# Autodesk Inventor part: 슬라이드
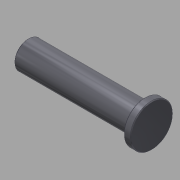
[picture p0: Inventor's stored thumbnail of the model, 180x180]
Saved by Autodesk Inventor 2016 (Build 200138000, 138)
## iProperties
Created: 2015-10
Part Number: 슬라이드
Document SubType Name: Modeling
Designer: mdu
Density: 7.86 g/cm^3
Material: 강철, 연강
Appearance: 강철 - 광택
Mass: 1603.27 g
Surface Area: 269.019 cm^2
Volume: 203.978 cm^3
Author: mdu
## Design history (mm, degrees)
sketch "스케치1"
  geometry: L1 (-75, 162)-(-75, 58) reference; L2 (-148, 110)-(22, 110); L3 (-148, 110)-(-148, 129); L4 (-148, 129)-(12, 129); L5 (12, 129)-(12, 139); L6 (12, 139)-(22, 139); L7 (22, 139)-(22, 110); 2 further points
  constraints: 12 end point, 3 parallel, 3 perpendicular, 1 midpoint, 1 point on line
  dimensions: "d0" = 58 diameter of L6 L2; "d1" = 38 diameter of L4 L2; "d2" = 10 distance of L5.end L6.end; "d3" = 170 distance of L2.start L2.end; "d4" = 73 distance between parallel lines of L3 L1
revolve "회전1" sketch "스케치1" stored, may be unused: angle "d5" = 90 deg
hole "구멍1" diameter "d11" = 13.376; stored, may be unused: countersink angle "d15" = 90 deg, drill point angle "d17" = 118 deg; dims "d9" = 10, "d10" = 10, "d12" = 22, "d13" = 4, "d14" = 2, "d16" = 25
chamfer "모따기1" distance "d6" = 1; stored, may be unused: second distance "d7" = 2, angle "d8" = 45 deg
node "솔리드1"
node "참조1"
